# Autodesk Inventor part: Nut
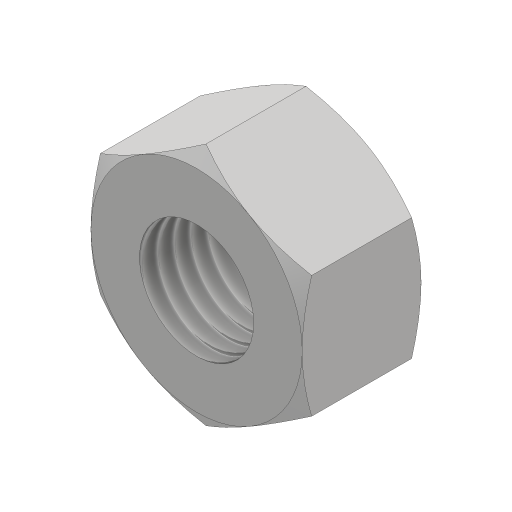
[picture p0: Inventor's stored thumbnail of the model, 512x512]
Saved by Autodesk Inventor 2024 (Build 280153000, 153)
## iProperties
Created: 2016-05
Part Number: Nut
Material: Generic
Document SubType Name: Modeling
Designer: CADCIM
Density: 1 g/cm^3
Appearance: Default
Author: CADCIM
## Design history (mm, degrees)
sketch "Sketch1"
  geometry: L1 (9.6, -5.543)-(0, -11.085); L2 (0, -11.085)-(-9.6, -5.543); L3 (-9.6, -5.543)-(-9.6, 5.543); L4 (-9.6, 5.543)-(0, 11.085); L5 (0, 11.085)-(9.6, 5.543); L6 (9.6, 5.543)-(9.6, -5.543); 2 further points
  constraints: 12 end point, 1 coincident, 1 vertical alignment, 13 other
  dimensions: "d0" = 19.2 distance between parallel lines of L3 L6
extrude "Extrusion1" new body sketch "Sketch1" distance "d1" = 10.8; taper "d2" = 0 deg
sketch "Sketch2"
  geometry: L1 (0, 11.085)-(-9.6, 5.543) reference; C1 r 9.6 at (0, 0); 1 further point
  constraints: 1 centre point, 1 coincident, 1 tangent
extrude "Extrusion2" sketch "Sketch2" distance "d3" = 10.8; taper "d4" = 60 deg
workplane "Work Plane1"
sketch "Sketch3"
  geometry: L1 (0, -11.085)-(9.6, -5.543) reference; C1 r 9.6 at (0, 0); 1 further point
  constraints: 1 centre point, 1 coincident, 1 tangent
extrude "Extrusion3" sketch "Sketch3" distance "d5" = 10.8; taper "d6" = 60 deg
hole "Hole1" diameter "d9" = 10.376; stored, may be unused: countersink angle "d13" = 90 deg, drill point angle "d15" = 118 deg; dims "d7" = 10, "d8" = 10, "d10" = 24, "d11" = 4, "d12" = 2, "d14" = 31.3
body "Solid1"
sketch "Sketch4"
  geometry: 1 further point
